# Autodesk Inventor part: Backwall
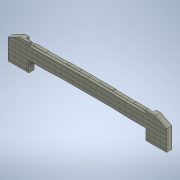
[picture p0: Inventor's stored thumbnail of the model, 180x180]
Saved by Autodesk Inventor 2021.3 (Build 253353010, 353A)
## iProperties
Created: 2021-11
Part Number: Backwall
Material: Concrete, Cast-in-Place, Gray
Document SubType Name: Modeling
Designer: u1426
Density: 2.40731 g/cm^3
Appearance: Flat - Gray 1
Author: u1426
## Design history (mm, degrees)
sketch "Sketch1"
  geometry: L1 (-5505.45, 0)-(-5505.45, 1016); L2 (5505.45, 0)-(5505.45, 1016); L3 (5505.45, 1016)-(3962.4, 1016); L4 (-5505.45, 1016)-(-3962.4, 1016); L5 (-3962.4, 1016)-(-2336.8, 1076.96); L6 (-2336.8, 1076.96)-(2336.8, 1076.96); L7 (2336.8, 1076.96)-(3962.4, 1016); L8 (-5505.45, 0)-(-7467.6, 0); L9 (-7467.6, 0)-(-7467.6, 1943.1); L10 (5505.45, 0)-(7467.6, 0); L11 (7467.6, 0)-(7467.6, 1936.75); L12 (6400.8, 2470.15)-(5486.4, 2470.15); L13 (5486.4, 2470.15)-(0, 2586.228); L14 (-6400.8, 2476.5)-(-5486.4, 2476.5); L15 (-5486.4, 2476.5)-(0, 2586.228); L16 (-6400.8, 2476.5)-(-7467.6, 1943.1); L17 (6400.8, 2470.15)-(7467.6, 1936.75); 3 further points
  constraints: 34 end point, 5 horizontal, 4 perpendicular, 4 point on line, 2 vertical, 1 collinear
  dimensions: "d0" = 5505.45 distance of point (0, 0) L1.start; "d4" = 1543.05 distance of L2.end L3.end; "d5" = 1543.05 distance of L1.end L4.end; "d6" = 1625.6 horizontal distance of L6.end L3.end; "d7" = 1625.6 horizontal distance of L4.end L5.end; "d8" = 4673.6 distance of L5.end L6.end (derived); "d9" = 2336.8 horizontal distance of L5.end point (0, 0) (derived); "d10" = 60.96 vertical distance of L4.end L5.end; "d30" = 5505.45 distance from line of point (0, 0) L2; "d31" = 1016 distance of L1.start L1.end; "d32" = 1016 distance of L2.start L2.end; "d33" = 1962.15 distance of L1.start L8.end; "d34" = 2476.5 distance of L8.end point (-7467.6, 2476.5); "d35" = 1962.15 distance of L2.start L10.end; "d36" = 2470.15 distance of L10.end point (7467.6, 2470.15); "d37" = 1981.2 distance of point (7467.6, 2470.15) L12.end; "d38" = 1981.2 distance of point (-7467.6, 2476.5) L14.end; "d39" = 5486.4 horizontal distance of L14.end L13.end; "d41" = 5486.4 horizontal distance of L12.end L13.end; "d42" = 109.728 vertical distance of L14.end L13.end; "d43" = 1066.8 distance of L14.start point (-7467.6, 2476.5); "d44" = 533.4 distance of L9.end point (-7467.6, 2476.5); "d45" = 1066.8 distance of L12.start point (7467.6, 2470.15) (= d43); "d46" = 533.4 distance of L11.end point (7467.6, 2470.15) (= d44)
extrude "Extrusion1" new body sketch "Sketch1" distance "d11" = 508; taper "d12" = 0 deg
sketch "Sketch3"
  geometry: L1 (0, 2586.228)-(-5486.4, 2476.5) reference; L2 (5486.4, 2470.15)-(0, 2586.228) reference; L3 (-5486.4, 2476.5)-(0, 2586.228) reference; L4 (-5486.4, 2476.5)-(-5486.4, 2171.7); L5 (5486.4, 2470.15)-(5486.4, 2165.35); L6 (5486.4, 2165.35)-(0, 2281.428); L7 (0, 2281.428)-(-5486.4, 2171.7); 1 further point
  constraints: 8 end point, 2 parallel, 2 vertical
  dimensions: "d47" = 304.8 distance of L1.end L4.end; "d48" = 304.8 distance of L2.start L5.end
extrude "Extrusion2" cut sketch "Sketch3" distance "d49" = 228.6; taper "d50" = 0 deg
sketch "Sketch4"
  geometry: L1 (-5505.45, 1016)-(-3962.4, 1016) reference; L2 (-3962.4, 1016)-(-2336.8, 1076.96) reference; L3 (-2336.8, 1076.96)-(2336.8, 1076.96) reference; L4 (2336.8, 1076.96)-(3962.4, 1016) reference; L5 (3962.4, 1016)-(5505.45, 1016) reference; L6 (5486.4, 1022.35)-(3962.519, 1022.35); L7 (3962.519, 1022.35)-(2336.919, 1083.31); L8 (2336.919, 1083.31)-(-2336.919, 1083.31); L9 (-2336.919, 1083.31)-(-3962.519, 1022.35); L10 (-3962.519, 1022.35)-(-5486.4, 1022.35); L11 (-5505.45, 0)-(-5505.45, 1016) reference; L12 (5486.4, 1016)-(5486.4, 1022.35); L13 (5505.45, 1016)-(5505.45, 0) reference; L14 (-3962.4, 1016)-(-5505.45, 1016) reference; L15 (-5486.4, 1016)-(-5486.4, 1022.35); 2 further points
  constraints: 14 end point, 2 perpendicular, 2 point on line, 2 other
  dimensions: "d51" = 6.35 distance between parallel lines of L3 L8; "d52" = 19.05 distance between parallel lines of L12 L13; "d53" = 19.05 distance between parallel lines of L15 L11
extrude "Extrusion3" cut sketch "Sketch4" distance "d54" = 76.2; taper "d55" = 0 deg
sketch "Sketch5"
  geometry: L1 (-5505.45, 1016)-(-3962.4, 1016) reference; L2 (-3962.4, 1016)-(-2336.8, 1076.96) reference; L3 (-2336.8, 1076.96)-(2336.8, 1076.96) reference; L4 (2336.8, 1076.96)-(3962.4, 1016) reference; L5 (3962.4, 1016)-(5505.45, 1016) reference; L6 (5486.4, 1022.35)-(3962.519, 1022.35); L7 (3962.519, 1022.35)-(2336.919, 1083.31); L8 (2336.919, 1083.31)-(-2336.919, 1083.31); L9 (-2336.919, 1083.31)-(-3962.519, 1022.35); L10 (-3962.519, 1022.35)-(-5486.4, 1022.35); L11 (-5486.4, 1022.35)-(-5486.4, 1016) reference; L12 (5486.4, 1016)-(5486.4, 1022.35) reference; 1 further point
  constraints: 10 end point, 2 point on line, 2 other
  dimensions: "d56" = 6.35 distance between parallel lines of L3 L8
extrude "Extrusion4" cut sketch "Sketch5" distance "d57" = 76.2; taper "d58" = 0 deg
sketch "Sketch6"
  geometry: L1 (0, 2586.228)-(-5486.4, 2470.15) reference; L2 (5486.4, 2476.5)-(0, 2586.228) reference; L3 (-5486.4, 2470.15)-(-5994.4, 2470.15); L4 (-5486.4, 2470.15)-(-6400.8, 2470.15) reference; L5 (-5994.4, 2470.15)-(-5994.4, 2266.95); L6 (5486.4, 2476.5)-(5994.4, 2476.5); L7 (5486.4, 2476.5)-(6400.8, 2476.5) reference; L8 (5994.4, 2476.5)-(5994.4, 2273.3); L9 (-5994.4, 2266.95)-(-5334, 2213.024); L10 (-5334, 2213.024)-(-5334, 2225.724); L11 (-5334, 2225.724)-(-4114.8, 2225.724); L12 (-4114.8, 2225.724)-(-4114.8, 2289.573); L13 (-4114.8, 2289.573)-(-2184.4, 2330.415); L14 (-2184.4, 2330.415)-(-2184.4, 2292.362); L15 (-2184.4, 2292.362)-(-965.2, 2292.362); L16 (-965.2, 2292.362)-(-965.2, 2356.21); L17 (-965.2, 2356.21)-(0.121, 2376.634); L18 (0.121, 2376.634)-(965.2, 2357.332); L19 (965.2, 2357.332)-(965.2, 2294.89); L20 (965.2, 2294.89)-(2184.4, 2294.89); L21 (2184.4, 2294.89)-(2184.4, 2332.948); L22 (2184.4, 2332.948)-(4114.8, 2294.34); L23 (4114.8, 2294.34)-(4114.8, 2231.898); L24 (4114.8, 2231.898)-(5334, 2231.898); L25 (5334, 2231.898)-(5334, 2219.198); L26 (5334, 2219.198)-(5994.4, 2273.3); L27 (-2184.4, 2292.362)-(-2184.4, 2540.012); L28 (2184.4, 2294.89)-(2184.4, 2542.54); L29 (5486.4, 2476.5)-(0, 2586.228) reference; L30 (5334, 2231.898)-(5334, 2479.548); L31 (-5334, 2225.724)-(-5334, 2473.374); L32 (-5994.4, 2190.496)-(-5334, 2136.571); L33 (-4114.8, 2213.356)-(-2184.4, 2254.198); L34 (-965.2, 2279.993)-(0.165, 2300.418); L35 (0.165, 2300.418)-(965.2, 2281.117); L36 (2184.4, 2256.733)-(4114.8, 2218.125); L37 (5334, 2142.743)-(5994.4, 2196.845); L38 (-5994.4, 2266.95)-(-5994.4, 2190.496); L39 (-5334, 2213.024)-(-5334, 2136.571); L40 (-4114.8, 2225.724)-(-4114.8, 2213.356); L41 (-2184.4, 2292.362)-(-2184.4, 2254.198); L42 (-965.2, 2292.362)-(-965.2, 2279.993); L43 (965.2, 2294.89)-(965.2, 2281.117); L44 (2184.4, 2294.89)-(2184.4, 2256.733); L45 (4114.8, 2231.898)-(4114.8, 2218.125); L46 (5334, 2219.198)-(5334, 2142.743); L47 (5994.4, 2273.3)-(5994.4, 2196.845); 1 further point
  constraints: 84 end point, 18 vertical, 7 parallel, 7 perpendicular, 6 point on line
  dimensions: "d59" = 508 distance of L1.end L3.end; "d60" = 203.2 distance of L3.end L5.end; "d61" = 508 distance of L2.start L6.end; "d63" = 203.2 distance of L6.end L8.end; "d64" = 12.7 distance of L9.end L10.end; "d65" = 1219.2 distance of L10.end L11.end; "d66" = 1219.2 distance of L14.end L15.end; "d67" = 1219.2 distance of L19.end L20.end; "d68" = 1219.2 distance of L23.end L24.end; "d69" = 12.7 distance of L24.end L25.end; "d70" = 209.55 distance between parallel lines of L18 L2; "d71" = 209.55 distance between parallel lines of L17 L1; "d72" = 209.55 distance between parallel lines of L13 L1; "d73" = 209.55 distance between parallel lines of L22 L2; "d77" = 247.65 distance of L14.end L27.end; "d78" = 247.65 distance of L20.end L28.end; "d79" = 247.65 distance of L10.end L31.end; "d81" = 247.65 distance of L24.end L30.end; "d84" = 1930.4 distance between parallel lines of L14 L12; "d85" = 965.2 distance from line of L1.start L16; "d86" = 965.2 distance from line of L1.start L19; "d87" = 1930.4 distance between parallel lines of L23 L21; "d88" = 76.2 distance between parallel lines of L37 L26; "d89" = 76.2 distance between parallel lines of L36 L22; "d90" = 76.2 distance between parallel lines of L35 L18; "d91" = 76.2 distance between parallel lines of L34 L17; "d92" = 76.2 distance between parallel lines of L33 L13; "d93" = 76.2 distance between parallel lines of L32 L9
extrude "Extrusion5" cut sketch "Sketch6" distance "d82" = 279.4; taper "d83" = 0 deg
body "Solid1"
